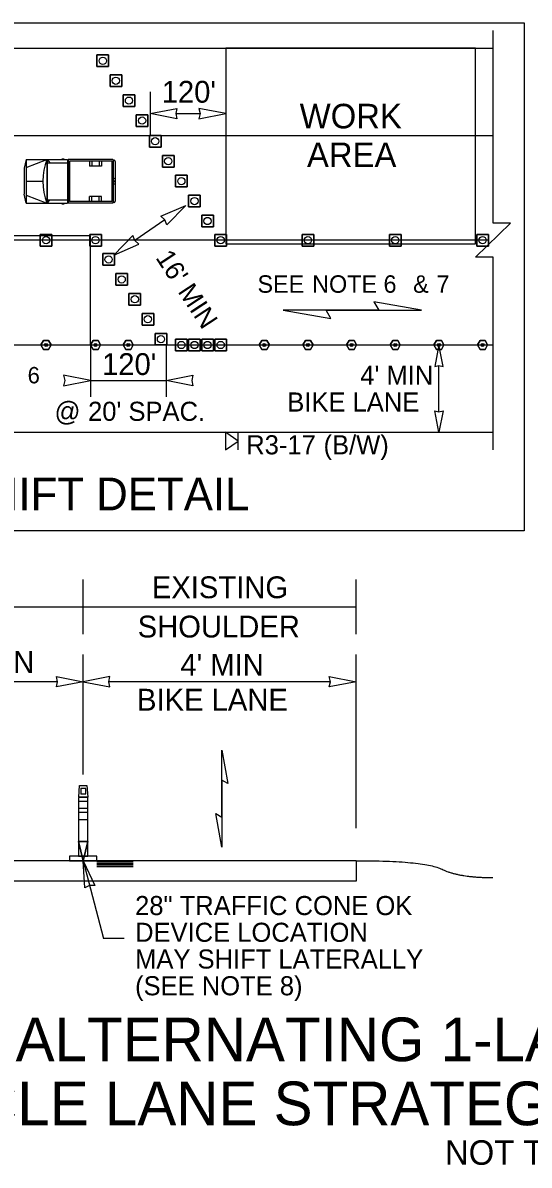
# Model space of a CAD drawing. Extents: x 99999.1 to 100095.7, y 99995 to 100010.7.
# Drawn here: x 100047.47 to 100049.325, y 100001.18 to 100005.366 of the extents above; entities that cross this region are included whole.
import ezdxf

# ---------------------------------------------------------------- set-up
doc = ezdxf.new("R2010")
doc.units = 0
for name, color, linetype in [('RD_ED_ShoulderPavedEdge', 7, 'Continuous'), ('RD_MK_LineEdgeWhite', 7, 'Continuous'), ('RD_MK_LineSkipCenter', 7, 'Continuous'), ('SH_DE_DetailHeading1Text', 7, 'Continuous'), ('SH_DE_DetailHeading2Text', 7, 'Continuous'), ('SH_TI_Tables', 7, 'Continuous'), ('TR_WZ_MotoristVehicle', 7, 'Continuous'), ('TR_WZ_PortableSignMountBlk-Wht', 7, 'Continuous'), ('TR_WZ_TrafficCone', 7, 'Continuous'), ('TR_WZ_TubularMarker', 7, 'Continuous'), ('TR_WZ_TubularMarkerElev', 7, 'Continuous'), ('TR_WZ_WorkZoneDetails', 7, 'Continuous'), ('TR_WZ_WorkZoneTextCurrent', 7, 'Continuous')]:
    doc.layers.add(name, color=color, linetype=linetype)

msp = doc.modelspace()

# ---------------------------------------------------------------- linework, layer by layer
at = {"layer": 'RD_ED_ShoulderPavedEdge'}
for p, q in [((100045.2759, 100005.2735), (100049.1933, 100005.2735)), ((100045.2759, 100003.8655), (100049.1933, 100003.8655))]:
    msp.add_line(p, q, dxfattribs=at)
at = {"layer": 'RD_MK_LineEdgeWhite'}
for p, q in [((100045.2759, 100004.9535), (100049.1933, 100004.9535)), ((100045.2759, 100004.1855), (100049.1933, 100004.1855))]:
    msp.add_line(p, q, dxfattribs=at)
at = {"layer": 'RD_MK_LineSkipCenter'}
msp.add_lwpolyline([(100049.1767, 100004.5695), (100045.2594, 100004.5695)], dxfattribs=at)
at = {"layer": 'SH_TI_Tables'}
msp.add_lwpolyline([(100045.1619, 100005.3662), (100049.3073, 100005.3662), (100049.3073, 100003.5045), (100045.1619, 100003.5045)], close=True, dxfattribs=at)
at = {"layer": 'TR_WZ_MotoristVehicle'}
for p, q in [((100047.482, 100004.8655), (100047.4746, 100004.8332)), ((100047.482, 100004.8655), (100047.482, 100004.7055)), ((100047.482, 100004.8655), (100047.6331, 100004.8655)), ((100047.482, 100004.8362), (100047.5576, 100004.8655)), ((100047.5576, 100004.8655), (100047.5576, 100004.7055)), ((100047.559, 100004.8655), (100047.559, 100004.7055)), ((100047.559, 100004.8655), (100047.5686, 100004.8531)), ((100047.6125, 100004.8677), (100047.6216, 100004.8677)), ((100047.6331, 100004.8655), (100047.6331, 100004.7055)), ((100047.7999, 100004.8655), (100047.6353, 100004.8655)), ((100047.6353, 100004.8655), (100047.6353, 100004.7055)), ((100047.7952, 100004.8591), (100047.64, 100004.8591)), ((100047.64, 100004.8591), (100047.64, 100004.7119)), ((100047.7142, 100004.8591), (100047.7142, 100004.8407)), ((100047.7222, 100004.8591), (100047.7222, 100004.8407)), ((100047.7494, 100004.8591), (100047.7494, 100004.8407)), ((100047.7582, 100004.8591), (100047.7582, 100004.8407)), ((100047.7952, 100004.8591), (100047.7952, 100004.7119)), ((100047.7999, 100004.8655), (100047.7999, 100004.7055)), ((100047.804, 100004.8629), (100047.8005, 100004.8629)), ((100047.8005, 100004.8629), (100047.8005, 100004.7081)), ((100047.4746, 100004.8332), (100047.4746, 100004.7378)), ((100047.559, 100004.8531), (100047.6331, 100004.8531)), ((100047.7582, 100004.8407), (100047.7142, 100004.8407)), ((100047.8076, 100004.858), (100047.8076, 100004.713)), ((100047.482, 100004.7855), (100047.5427, 100004.7855)), ((100047.8076, 100004.7968), (100047.8005, 100004.7938)), ((100047.8076, 100004.7742), (100047.8005, 100004.7772)), ((100047.8057, 100004.7855), (100047.8024, 100004.7855)), ((100047.804, 100004.7877), (100047.804, 100004.7832)), ((100047.482, 100004.7055), (100047.4746, 100004.7378)), ((100047.482, 100004.7348), (100047.5576, 100004.7055)), ((100047.482, 100004.7055), (100047.6331, 100004.7055)), ((100047.559, 100004.7179), (100047.6331, 100004.7179)), ((100047.5669, 100004.7179), (100047.559, 100004.7055)), ((100047.6125, 100004.7032), (100047.6216, 100004.7032)), ((100047.7999, 100004.7055), (100047.6353, 100004.7055)), ((100047.7952, 100004.7119), (100047.64, 100004.7119)), ((100047.7142, 100004.7119), (100047.7142, 100004.7303)), ((100047.7582, 100004.7303), (100047.7142, 100004.7303)), ((100047.7222, 100004.7119), (100047.7222, 100004.7303)), ((100047.7494, 100004.7119), (100047.7494, 100004.7303)), ((100047.7582, 100004.7119), (100047.7582, 100004.7303)), ((100047.804, 100004.7081), (100047.8005, 100004.7081))]:
    msp.add_line(p, q, dxfattribs=at)
for centre, major_axis, start_param, end_param in [((100047.6656, 100004.7855), (0, -0.1679), 4.215667, 5.208926), ((100047.804, 100004.858), (0, 0.00488), 4.712389, 6.283185), ((100047.804, 100004.713), (0, -0.00488), 0, 1.570796)]:
    msp.add_ellipse(centre, major_axis=major_axis, ratio=0.73155, start_param=start_param, end_param=end_param, dxfattribs=at)
msp.add_ellipse((100047.804, 100004.7855), major_axis=(0, 0.00225), ratio=0.73155, dxfattribs=at)
at = {"layer": 'TR_WZ_PortableSignMountBlk-Wht'}
msp.add_line((100048.2589, 100003.8011), (100048.2589, 100003.8655), dxfattribs=at)
msp.add_lwpolyline([(100048.2589, 100003.8333), (100048.2127, 100003.8655), (100048.2127, 100003.8011)], close=True, dxfattribs=at)
at = {"layer": 'TR_WZ_TrafficCone'}
for points in [[(100047.7413, 100005.2484), (100047.7839, 100005.2484), (100047.7839, 100005.2058), (100047.7413, 100005.2058), (100047.7413, 100005.2484)], [(100047.7413, 100005.2058), (100047.7839, 100005.2058), (100047.7839, 100005.2484), (100047.7413, 100005.2484), (100047.7413, 100005.2058)], [(100047.7893, 100005.1754), (100047.8319, 100005.1754), (100047.8319, 100005.1327), (100047.7893, 100005.1327), (100047.7893, 100005.1754)], [(100047.7893, 100005.1327), (100047.8319, 100005.1327), (100047.8319, 100005.1754), (100047.7893, 100005.1754), (100047.7893, 100005.1327)], [(100047.8373, 100005.1023), (100047.8799, 100005.1023), (100047.8799, 100005.0596), (100047.8373, 100005.0596), (100047.8373, 100005.1023)], [(100047.8373, 100005.0596), (100047.8799, 100005.0596), (100047.8799, 100005.1023), (100047.8373, 100005.1023), (100047.8373, 100005.0596)], [(100047.8853, 100005.0292), (100047.9279, 100005.0292), (100047.9279, 100004.9866), (100047.8853, 100004.9866), (100047.8853, 100005.0292)], [(100047.8853, 100004.9866), (100047.9279, 100004.9866), (100047.9279, 100005.0292), (100047.8853, 100005.0292), (100047.8853, 100004.9866)], [(100047.9333, 100004.9535), (100047.976, 100004.9535), (100047.976, 100004.9108), (100047.9333, 100004.9108), (100047.9333, 100004.9535)], [(100047.9333, 100004.9108), (100047.976, 100004.9108), (100047.976, 100004.9535), (100047.9333, 100004.9535), (100047.9333, 100004.9108)], [(100047.9813, 100004.8804), (100048.024, 100004.8804), (100048.024, 100004.8378), (100047.9813, 100004.8378), (100047.9813, 100004.8804)], [(100047.9813, 100004.8378), (100048.024, 100004.8378), (100048.024, 100004.8804), (100047.9813, 100004.8804), (100047.9813, 100004.8378)], [(100048.0293, 100004.8074), (100048.072, 100004.8074), (100048.072, 100004.7647), (100048.0293, 100004.7647), (100048.0293, 100004.8074)], [(100048.0293, 100004.7647), (100048.072, 100004.7647), (100048.072, 100004.8074), (100048.0293, 100004.8074), (100048.0293, 100004.7647)], [(100048.0773, 100004.7343), (100048.12, 100004.7343), (100048.12, 100004.6916), (100048.0773, 100004.6916), (100048.0773, 100004.7343)], [(100048.0773, 100004.6916), (100048.12, 100004.6916), (100048.12, 100004.7343), (100048.0773, 100004.7343), (100048.0773, 100004.6916)], [(100048.1253, 100004.6612), (100048.168, 100004.6612), (100048.168, 100004.6186), (100048.1253, 100004.6186), (100048.1253, 100004.6612)], [(100048.1253, 100004.6186), (100048.168, 100004.6186), (100048.168, 100004.6612), (100048.1253, 100004.6612), (100048.1253, 100004.6186)], [(100047.5333, 100004.5908), (100047.5759, 100004.5908), (100047.5759, 100004.5482), (100047.5333, 100004.5482), (100047.5333, 100004.5908)], [(100047.5333, 100004.5482), (100047.5759, 100004.5482), (100047.5759, 100004.5908), (100047.5333, 100004.5908), (100047.5333, 100004.5482)], [(100047.7147, 100004.5908), (100047.7573, 100004.5908), (100047.7573, 100004.5482), (100047.7147, 100004.5482), (100047.7147, 100004.5908)], [(100047.7147, 100004.5482), (100047.7573, 100004.5482), (100047.7573, 100004.5908), (100047.7147, 100004.5908), (100047.7147, 100004.5482)], [(100048.2159, 100004.5908), (100048.1732, 100004.5908), (100048.1732, 100004.5482), (100048.2159, 100004.5482), (100048.2159, 100004.5908)], [(100048.2159, 100004.5482), (100048.1732, 100004.5482), (100048.1732, 100004.5908), (100048.2159, 100004.5908), (100048.2159, 100004.5482)], [(100048.4933, 100004.5908), (100048.5359, 100004.5908), (100048.5359, 100004.5482), (100048.4933, 100004.5482), (100048.4933, 100004.5908)], [(100048.4933, 100004.5482), (100048.5359, 100004.5482), (100048.5359, 100004.5908), (100048.4933, 100004.5908), (100048.4933, 100004.5482)], [(100048.8133, 100004.5908), (100048.8559, 100004.5908), (100048.8559, 100004.5482), (100048.8133, 100004.5482), (100048.8133, 100004.5908)], [(100048.8133, 100004.5482), (100048.8559, 100004.5482), (100048.8559, 100004.5908), (100048.8133, 100004.5908), (100048.8133, 100004.5482)], [(100049.1333, 100004.5908), (100049.1759, 100004.5908), (100049.1759, 100004.5482), (100049.1333, 100004.5482), (100049.1333, 100004.5908)], [(100049.1333, 100004.5482), (100049.1759, 100004.5482), (100049.1759, 100004.5908), (100049.1333, 100004.5908), (100049.1333, 100004.5482)], [(100047.8053, 100004.4778), (100047.7626, 100004.4778), (100047.7626, 100004.5204), (100047.8053, 100004.5204), (100047.8053, 100004.4778)], [(100047.8053, 100004.5204), (100047.7626, 100004.5204), (100047.7626, 100004.4778), (100047.8053, 100004.4778), (100047.8053, 100004.5204)], [(100047.8533, 100004.4047), (100047.8106, 100004.4047), (100047.8106, 100004.4474), (100047.8533, 100004.4474), (100047.8533, 100004.4047)], [(100047.8533, 100004.4474), (100047.8106, 100004.4474), (100047.8106, 100004.4047), (100047.8533, 100004.4047), (100047.8533, 100004.4474)], [(100047.9013, 100004.3316), (100047.8586, 100004.3316), (100047.8586, 100004.3743), (100047.9013, 100004.3743), (100047.9013, 100004.3316)], [(100047.9013, 100004.3743), (100047.8586, 100004.3743), (100047.8586, 100004.3316), (100047.9013, 100004.3316), (100047.9013, 100004.3743)], [(100047.9493, 100004.2586), (100047.9066, 100004.2586), (100047.9066, 100004.3012), (100047.9493, 100004.3012), (100047.9493, 100004.2586)], [(100047.9493, 100004.3012), (100047.9066, 100004.3012), (100047.9066, 100004.2586), (100047.9493, 100004.2586), (100047.9493, 100004.3012)], [(100047.9973, 100004.1855), (100047.9546, 100004.1855), (100047.9546, 100004.2282), (100047.9973, 100004.2282), (100047.9973, 100004.1855)], [(100047.9973, 100004.2282), (100047.9546, 100004.2282), (100047.9546, 100004.1855), (100047.9973, 100004.1855), (100047.9973, 100004.2282)], [(100048.072, 100004.2068), (100048.0293, 100004.2068), (100048.0293, 100004.1642), (100048.072, 100004.1642), (100048.072, 100004.2068)], [(100048.072, 100004.1642), (100048.0293, 100004.1642), (100048.0293, 100004.2068), (100048.072, 100004.2068), (100048.072, 100004.1642)], [(100048.12, 100004.2068), (100048.0773, 100004.2068), (100048.0773, 100004.1642), (100048.12, 100004.1642), (100048.12, 100004.2068)], [(100048.12, 100004.1642), (100048.0773, 100004.1642), (100048.0773, 100004.2068), (100048.12, 100004.2068), (100048.12, 100004.1642)], [(100048.168, 100004.2068), (100048.1253, 100004.2068), (100048.1253, 100004.1642), (100048.168, 100004.1642), (100048.168, 100004.2068)], [(100048.168, 100004.1642), (100048.1253, 100004.1642), (100048.1253, 100004.2068), (100048.168, 100004.2068), (100048.168, 100004.1642)], [(100048.1732, 100004.2068), (100048.2159, 100004.2068), (100048.2159, 100004.1642), (100048.1732, 100004.1642), (100048.1732, 100004.2068)], [(100048.1732, 100004.1642), (100048.2159, 100004.1642), (100048.2159, 100004.2068), (100048.1732, 100004.2068), (100048.1732, 100004.1642)]]:
    msp.add_lwpolyline(points, dxfattribs=at)
for centre in [(100047.7626, 100005.2271), (100047.8106, 100005.154), (100047.8586, 100005.081), (100047.9066, 100005.0079), (100047.9546, 100004.9322), (100048.0026, 100004.8591), (100048.0506, 100004.786), (100048.0986, 100004.713), (100048.1466, 100004.6399), (100047.5546, 100004.5695), (100047.736, 100004.5695), (100048.1946, 100004.5695), (100048.5146, 100004.5695), (100048.8346, 100004.5695), (100049.1546, 100004.5695), (100047.7839, 100004.4991), (100047.8319, 100004.426), (100047.8799, 100004.353), (100047.9279, 100004.2799), (100047.9759, 100004.2068), (100048.0506, 100004.1855), (100048.0986, 100004.1855), (100048.1466, 100004.1855), (100048.1946, 100004.1855)]:
    msp.add_circle(centre, 0.0133, dxfattribs=at)
at = {"layer": 'TR_WZ_TubularMarker'}
for points in [[(100047.5731, 100004.1855), (100047.5638, 100004.2015), (100047.5454, 100004.2015), (100047.5361, 100004.1855), (100047.5454, 100004.1695), (100047.5638, 100004.1695)], [(100047.7545, 100004.1855), (100047.7452, 100004.2015), (100047.7268, 100004.2015), (100047.7175, 100004.1855), (100047.7268, 100004.1695), (100047.7452, 100004.1695)], [(100047.8744, 100004.1855), (100047.8652, 100004.2015), (100047.8467, 100004.2015), (100047.8375, 100004.1855), (100047.8467, 100004.1695), (100047.8652, 100004.1695)], [(100048.3361, 100004.1855), (100048.3454, 100004.2015), (100048.3639, 100004.2015), (100048.3731, 100004.1855), (100048.3639, 100004.1695), (100048.3454, 100004.1695)], [(100048.4961, 100004.1855), (100048.5054, 100004.2015), (100048.5239, 100004.2015), (100048.5331, 100004.1855), (100048.5239, 100004.1695), (100048.5054, 100004.1695)], [(100048.6561, 100004.1855), (100048.6654, 100004.2015), (100048.6839, 100004.2015), (100048.6931, 100004.1855), (100048.6839, 100004.1695), (100048.6654, 100004.1695)], [(100048.8161, 100004.1855), (100048.8254, 100004.2015), (100048.8439, 100004.2015), (100048.8531, 100004.1855), (100048.8439, 100004.1695), (100048.8254, 100004.1695)], [(100048.9761, 100004.1855), (100048.9854, 100004.2015), (100049.0039, 100004.2015), (100049.0131, 100004.1855), (100049.0039, 100004.1695), (100048.9854, 100004.1695)], [(100049.1361, 100004.1855), (100049.1454, 100004.2015), (100049.1638, 100004.2015), (100049.1731, 100004.1855), (100049.1638, 100004.1695), (100049.1454, 100004.1695)]]:
    msp.add_lwpolyline(points, close=True, dxfattribs=at)
for points in [[(100047.5638, 100004.1695), (100047.5454, 100004.1695), (100047.5361, 100004.1855), (100047.5454, 100004.2015), (100047.5638, 100004.2015), (100047.5731, 100004.1855), (100047.5638, 100004.1695)], [(100047.7452, 100004.1695), (100047.7268, 100004.1695), (100047.7175, 100004.1855), (100047.7268, 100004.2015), (100047.7452, 100004.2015), (100047.7545, 100004.1855), (100047.7452, 100004.1695)], [(100047.8652, 100004.1695), (100047.8467, 100004.1695), (100047.8375, 100004.1855), (100047.8467, 100004.2015), (100047.8652, 100004.2015), (100047.8744, 100004.1855), (100047.8652, 100004.1695)], [(100048.3454, 100004.1695), (100048.3639, 100004.1695), (100048.3731, 100004.1855), (100048.3639, 100004.2015), (100048.3454, 100004.2015), (100048.3361, 100004.1855), (100048.3454, 100004.1695)], [(100048.5054, 100004.1695), (100048.5239, 100004.1695), (100048.5331, 100004.1855), (100048.5239, 100004.2015), (100048.5054, 100004.2015), (100048.4961, 100004.1855), (100048.5054, 100004.1695)], [(100048.6654, 100004.1695), (100048.6839, 100004.1695), (100048.6931, 100004.1855), (100048.6839, 100004.2015), (100048.6654, 100004.2015), (100048.6561, 100004.1855), (100048.6654, 100004.1695)], [(100048.8254, 100004.1695), (100048.8439, 100004.1695), (100048.8531, 100004.1855), (100048.8439, 100004.2015), (100048.8254, 100004.2015), (100048.8161, 100004.1855), (100048.8254, 100004.1695)], [(100048.9854, 100004.1695), (100049.0039, 100004.1695), (100049.0131, 100004.1855), (100049.0039, 100004.2015), (100048.9854, 100004.2015), (100048.9761, 100004.1855), (100048.9854, 100004.1695)], [(100049.1454, 100004.1695), (100049.1638, 100004.1695), (100049.1731, 100004.1855), (100049.1638, 100004.2015), (100049.1454, 100004.2015), (100049.1361, 100004.1855), (100049.1454, 100004.1695)]]:
    msp.add_lwpolyline(points, dxfattribs=at)
for centre in [(100047.5546, 100004.1855), (100047.736, 100004.1855), (100047.856, 100004.1855), (100048.3546, 100004.1855), (100048.5146, 100004.1855), (100048.6746, 100004.1855), (100048.8346, 100004.1855), (100048.9946, 100004.1855), (100049.1546, 100004.1855)]:
    msp.add_circle(centre, 0.00533, dxfattribs=at)
at = {"layer": 'TR_WZ_TubularMarkerElev'}
for p, q in [((100047.6824, 100002.5612), (100047.6998, 100002.5612)), ((100047.6743, 100002.5288), (100047.7072, 100002.5288)), ((100047.6998, 100002.539), (100047.6824, 100002.539)), ((100047.7074, 100002.5125), (100047.6741, 100002.5125)), ((100047.6741, 100002.5125), (100047.6741, 100002.4879)), ((100047.6741, 100002.4879), (100047.7074, 100002.4879)), ((100047.7074, 100002.4879), (100047.7074, 100002.5125)), ((100047.6741, 100002.4715), (100047.6741, 100002.447)), ((100047.7074, 100002.4715), (100047.6741, 100002.4715)), ((100047.6741, 100002.447), (100047.7074, 100002.447)), ((100047.7074, 100002.447), (100047.7074, 100002.4715)), ((100047.6408, 100002.3119), (100047.6408, 100002.2955)), ((100047.7408, 100002.2955), (100047.7408, 100002.3119)), ((100047.6408, 100002.2955), (100047.7408, 100002.2955))]:
    msp.add_line(p, q, dxfattribs=at)
msp.add_lwpolyline([(100047.6743, 100002.5288), (100047.6774, 100002.5713), (100047.7044, 100002.5713), (100047.7072, 100002.5288)], close=True, dxfattribs=at)
for points in [[(100047.6741, 100002.3119), (100047.7074, 100002.3119), (100047.7074, 100002.5247)], [(100047.6741, 100002.5247), (100047.6741, 100002.3119)], [(100047.6741, 100002.3119), (100047.7074, 100002.3119), (100047.7074, 100002.5247)], [(100047.6741, 100002.5247), (100047.6741, 100002.3119)], [(100047.7072, 100002.5288), (100047.6743, 100002.5288), (100047.7072, 100002.5288), (100047.6743, 100002.5288)], [(100047.7072, 100002.5288), (100047.6743, 100002.5288), (100047.7072, 100002.5288), (100047.6743, 100002.5288)], [(100047.7408, 100002.3119), (100047.7074, 100002.3119), (100047.6741, 100002.3119), (100047.6408, 100002.3119)]]:
    msp.add_lwpolyline(points, dxfattribs=at)
for centre, major_axis, ratio, start_param, end_param in [((100047.6824, 100002.5501), (0, 0.0111), 0.071484, 0, 3.141593), ((100047.6998, 100002.5501), (0, 0.0111), 0.071484, 3.141593, 6.283185), ((100047.6744, 100002.5238), (0, 0.00512), 0.053405, 0.177149, 1.393647), ((100047.6744, 100002.5238), (0, 0.00512), 0.053405, 0.177149, 1.393647), ((100047.7072, 100002.5238), (0, 0.00512), 0.053405, 4.889538, 6.106036), ((100047.7072, 100002.5238), (0, 0.00512), 0.053405, 4.889538, 6.106036)]:
    msp.add_ellipse(centre, major_axis=major_axis, ratio=ratio, start_param=start_param, end_param=end_param, dxfattribs=at)
at = {"layer": 'TR_WZ_WorkZoneDetails'}
for p, q in [((100047.9359, 100005.1135), (100047.9359, 100004.9535)), ((100048.2133, 100005.1135), (100048.2133, 100004.9535)), ((100048.0297, 100005.0335), (100048.1195, 100005.0335)), ((100047.9897, 100004.6438), (100047.8798, 100004.5682)), ((100048.581, 100004.3129), (100048.7739, 100004.3129)), ((100048.7739, 100004.3129), (100048.581, 100004.3129)), ((100047.7173, 100004.1855), (100047.7173, 100003.9955)), ((100047.9946, 100004.1855), (100047.9946, 100003.9955)), ((100048.9946, 100003.9405), (100048.9946, 100004.1105)), ((100047.7173, 100004.0555), (100047.9946, 100004.0555)), ((100047.6907, 100003.1255), (100047.6907, 100003.3255)), ((100048.6907, 100003.1255), (100048.6907, 100003.3255)), ((100046.4907, 100003.2255), (100047.6907, 100003.2255)), ((100047.6907, 100003.2255), (100048.6907, 100003.2255)), ((100047.6907, 100002.6113), (100047.6907, 100003.0515)), ((100048.6907, 100002.4152), (100048.6907, 100003.0515)), ((100047.5969, 100002.9515), (100046.5844, 100002.9515)), ((100048.597, 100002.9515), (100047.7844, 100002.9515)), ((100048.199, 100002.5906), (100048.199, 100002.4555)), ((100048.199, 100002.4555), (100048.199, 100002.5906)), ((100048.6907, 100002.2954), (100044.2907, 100002.2954)), ((100047.6907, 100002.2954), (100047.7647, 100002.0101)), ((100047.8737, 100002.2898), (100047.7407, 100002.2898)), ((100047.8737, 100002.2842), (100047.7407, 100002.2842)), ((100047.8737, 100002.2785), (100047.7407, 100002.2785)), ((100047.8737, 100002.2733), (100047.7407, 100002.2733)), ((100048.6907, 100002.2954), (100048.6907, 100002.2204)), ((100048.6907, 100002.2204), (100044.2907, 100002.2204)), ((100047.841, 100002.0101), (100047.7647, 100002.0101))]:
    msp.add_line(p, q, dxfattribs=at)
for points in [[(100049.1933, 100003.8015), (100049.1933, 100004.5075), (100049.1292, 100004.5075), (100049.2573, 100004.6314), (100049.1933, 100004.6314), (100049.1933, 100005.3375)], [(100047.7073, 100002.3652), (100047.674, 100002.3652), (100047.6907, 100002.2954), (100047.7073, 100002.3652)]]:
    msp.add_lwpolyline(points, dxfattribs=at)
for points in [[(100048.2133, 100005.2735), (100048.2133, 100004.5562), (100049.1292, 100004.5562), (100049.1292, 100005.2735)], [(100047.9359, 100005.0335), (100048.0342, 100005.0528), (100048.0297, 100005.0335), (100048.0342, 100005.0142)], [(100048.2133, 100005.0335), (100048.115, 100005.0528), (100048.1195, 100005.0335), (100048.115, 100005.0142)], [(100048.0669, 100004.697), (100047.9969, 100004.6254), (100047.9897, 100004.6438), (100047.975, 100004.6571)], [(100046.7389, 100004.5855), (100046.7389, 100004.1855), (100047.7173, 100004.1855), (100047.7173, 100004.5855)], [(100047.8026, 100004.5151), (100047.8945, 100004.5549), (100047.8798, 100004.5682), (100047.8727, 100004.5867)], [(100048.9311, 100004.3129), (100048.756, 100004.3438), (100048.7739, 100004.3129)], [(100048.4238, 100004.3129), (100048.5988, 100004.2821), (100048.581, 100004.3129)], [(100048.9946, 100004.1855), (100048.9792, 100004.1069), (100048.9946, 100004.1105), (100049.01, 100004.1069)], [(100047.7173, 100004.0555), (100047.619, 100004.0748), (100047.6236, 100004.0555), (100047.619, 100004.0362)], [(100047.9946, 100004.0555), (100048.0929, 100004.0748), (100048.0884, 100004.0555), (100048.0929, 100004.0362)], [(100048.9946, 100003.8655), (100048.9792, 100003.9441), (100048.9946, 100003.9405), (100049.01, 100003.9441)], [(100047.6907, 100002.9515), (100047.5924, 100002.9322), (100047.5969, 100002.9515), (100047.5924, 100002.9708)], [(100047.6907, 100002.9515), (100047.7889, 100002.9322), (100047.7844, 100002.9515), (100047.7889, 100002.9708)], [(100048.6907, 100002.9515), (100048.5924, 100002.9322), (100048.597, 100002.9515), (100048.5924, 100002.9708)], [(100048.199, 100002.7007), (100048.2206, 100002.5781), (100048.199, 100002.5906)], [(100048.199, 100002.3454), (100048.1774, 100002.468), (100048.199, 100002.4555)], [(100047.6907, 100002.2954), (100047.674, 100002.3652), (100047.7073, 100002.3652)], [(100047.6907, 100002.2954), (100047.734, 100002.2051), (100047.7142, 100002.2047), (100047.6967, 100002.1955)]]:
    msp.add_lwpolyline(points, close=True, dxfattribs=at)
msp.add_open_spline([(100048.6907, 100002.2954), (100048.9419, 100002.2956), (100049.0674, 100002.2335), (100049.1928, 100002.2336)], degree=2, dxfattribs=at)

# ---------------------------------------------------------------- texts
at = {"layer": 'SH_DE_DetailHeading1Text'}
for s, height, p in [('PILOT CAR OPERATION FOR ALTERNATING 1-LANE, 2-WAY TRAFFIC: AFAD-CONTROLLED', 0.16, (100044.4237, 100001.5606)), ('SEPARATED BICYCLE LANE STRATEGY (HIGHWAYS, 40 MPH OR LESS)', 0.16, (100045.4399, 100001.3259)), ('NOT TO SCALE', 0.09, (100049.0168, 100001.1809))]:
    msp.add_text(s, height=height, rotation=360, dxfattribs=at).set_placement(p)
at = {"layer": 'SH_DE_DetailHeading2Text'}
msp.add_text('OPTIONAL LANE SHIFT DETAIL', height=0.12, rotation=360, dxfattribs=at).set_placement((100045.9105, 100003.5795))
at = {"layer": 'TR_WZ_WorkZoneDetails'}
for s, height, p in [('WORK', 0.09, (100048.4843, 100004.9794)), ('AREA', 0.09, (100048.511, 100004.8376)), ('R3-17', 0.07, (100048.2884, 100003.7847)), ('(B/W)', 0.07, (100048.5718, 100003.7847)), ("10' MIN LANE OPEN", 0.08, (100046.5043, 100002.9835)), ("4' MIN", 0.08, (100048.0471, 100002.9735)), ('BIKE LANE', 0.08, (100047.8881, 100002.8455))]:
    msp.add_text(s, height=height, dxfattribs=at).set_placement(p)
for s, p in [('EXISTING', (100047.9424, 100003.2575)), ('SHOULDER', (100047.8905, 100003.1135))]:
    msp.add_text(s, height=0.08, rotation=360, dxfattribs=at).set_placement(p)
at = {"layer": 'TR_WZ_WorkZoneTextCurrent'}
for s, height, rotation, p in [("120'", 0.08, 360, (100047.9785, 100005.0735)), ("16' MIN", 0.07, 303.3023, (100047.9542, 100004.5052)), ("120'", 0.08, 360, (100047.7598, 100004.0755)), ('@', 0.07, 360, (100047.5857, 100003.9075)), ("20' SPAC.", 0.07, 360, (100047.7086, 100003.9075))]:
    msp.add_text(s, height=height, rotation=rotation, dxfattribs=at).set_placement(p)
for s, height, p in [('SEE', 0.064, (100048.3296, 100004.3769)), ('NOTE 6', 0.064, (100048.53, 100004.3769)), ('&', 0.064, (100048.9002, 100004.3769)), ('7', 0.064, (100048.9859, 100004.3769)), ('6', 0.06, (100047.4872, 100004.0449)), ("4' MIN", 0.07, (100048.7064, 100004.0395)), ('BIKE LANE', 0.07, (100048.4388, 100003.9415)), ('28" TRAFFIC CONE OK', 0.07, (100047.881, 100002.0961)), ('DEVICE LOCATION', 0.07, (100047.881, 100001.9981)), ('MAY SHIFT LATERALLY ', 0.07, (100047.881, 100001.9001)), ('(SEE NOTE 8)', 0.07, (100047.881, 100001.8021))]:
    msp.add_text(s, height=height, dxfattribs=at).set_placement(p)

doc.saveas('drawing.dxf')
